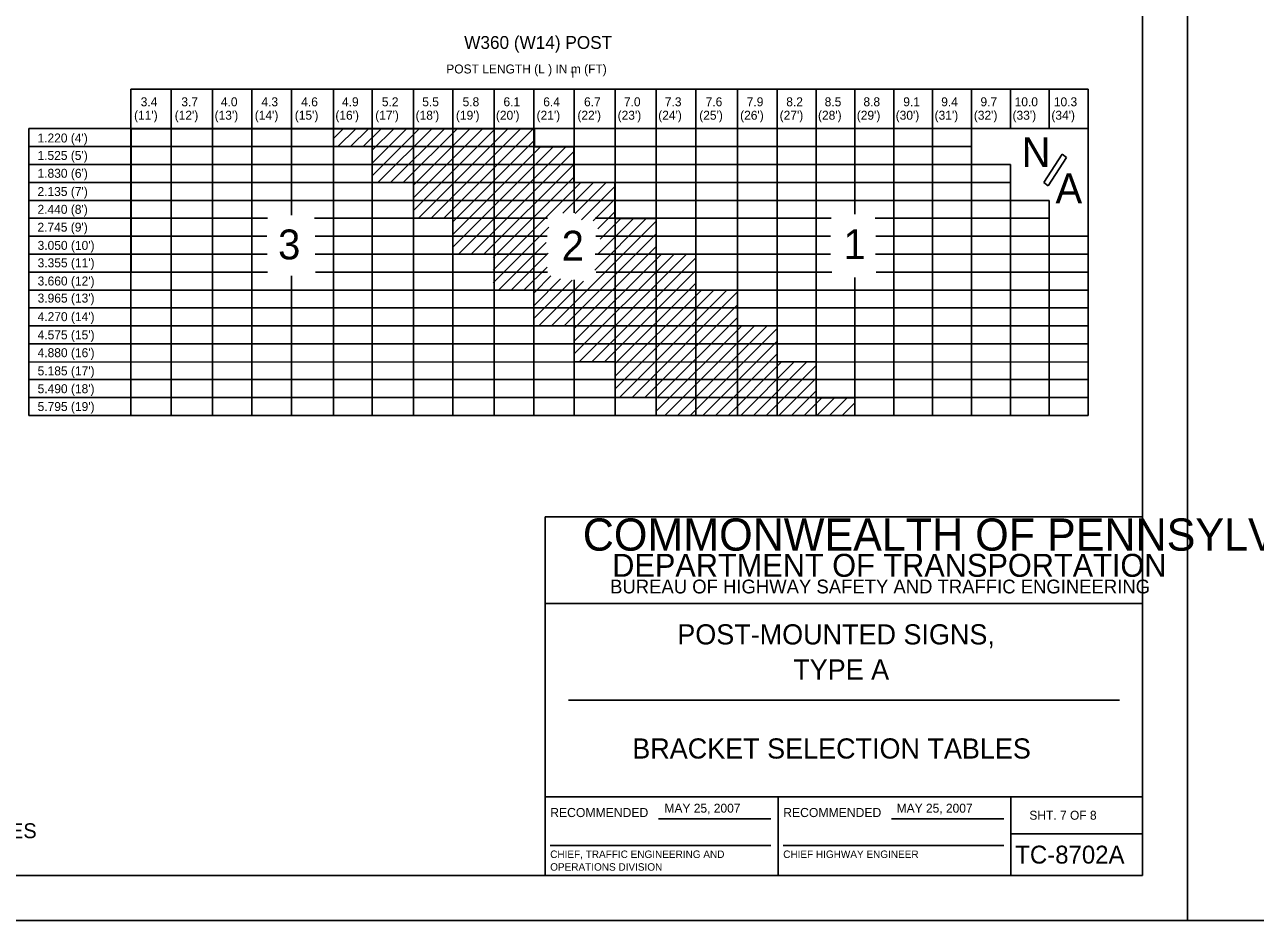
# Model space of a CAD drawing. Extents: x 637580 to 641008, y 294594 to 295782.
# Drawn here: x 639714 to 640126.1, y 294593.6 to 294893.4 of the extents above; entities that cross this region are included whole.
import ezdxf

# ---------------------------------------------------------------- set-up
doc = ezdxf.new("R2010")
doc.units = 0
for name, color, linetype in [('1', 7, 'Continuous'), ('2', 7, 'Continuous'), ('PLT-BNDY', 7, 'Continuous')]:
    doc.layers.add(name, color=color, linetype=linetype)

msp = doc.modelspace()

# ---------------------------------------------------------------- linework, layer by layer
at = {"layer": '1'}
for p, q in [((640088.31, 294608.63), (640088.31, 295172.63)), ((639888.31, 294608.63), (639888.31, 294728.63)), ((639888.31, 294728.63), (640088.31, 294728.63)), ((640088.31, 294699.63), (639888.31, 294699.63)), ((639896.06, 294667.31), (640080.56, 294667.31)), ((639888.31, 294635), (640088.31, 294635)), ((639966.31, 294635), (639966.31, 294608.63)), ((640044.19, 294608.63), (640044.19, 294635)), ((639926.24, 294627.57), (639963.87, 294627.57)), ((640004.24, 294627.57), (640041.87, 294627.57)), ((640044.19, 294622.63), (640088.31, 294622.63)), ((639889.99, 294618.68), (639963.87, 294618.68)), ((639967.99, 294618.68), (640041.87, 294618.68)), ((640088.31, 294608.63), (639302.31, 294608.63)), ((639302.31, 294608.63), (639888.31, 294608.63))]:
    msp.add_line(p, q, dxfattribs=at)
at = {"layer": '2'}
for p, q in [((640070.04, 294871.85), (639749.64, 294871.85)), ((639749.64, 294871.85), (639749.64, 294762.59)), ((639763.15, 294871.85), (639763.15, 294762.59)), ((639776.9, 294871.85), (639776.9, 294762.59)), ((639790.16, 294871.85), (639790.16, 294762.59)), ((639803.42, 294871.85), (639803.42, 294829.67)), ((639817.42, 294871.85), (639817.42, 294762.59)), ((639830.43, 294871.85), (639830.43, 294762.59)), ((639844.19, 294871.85), (639844.19, 294762.59)), ((639857.44, 294871.85), (639857.44, 294762.59)), ((639871.2, 294871.85), (639871.2, 294762.59)), ((639884.46, 294871.85), (639884.46, 294762.59)), ((639897.97, 294871.85), (639897.97, 294830.38)), ((639911.72, 294871.85), (639911.72, 294762.59)), ((639925.48, 294871.85), (639925.48, 294762.59)), ((639938.74, 294871.85), (639938.74, 294762.59)), ((639952.74, 294871.85), (639952.74, 294762.59)), ((639966, 294871.85), (639966, 294762.59)), ((639979.01, 294871.85), (639979.01, 294762.59)), ((639992.01, 294871.85), (639992.01, 294829.95)), ((640005.02, 294871.85), (640005.02, 294762.59)), ((640018.02, 294871.85), (640018.02, 294762.59)), ((640031.03, 294871.85), (640031.03, 294762.59)), ((640044.03, 294871.85), (640044.03, 294858.59)), ((640057.04, 294871.85), (640057.04, 294858.59)), ((640070.04, 294871.85), (640070.04, 294762.59)), ((640070.04, 294858.59), (639715.41, 294858.59)), ((639715.41, 294858.59), (639715.41, 294762.59)), ((639749.75, 294858.57), (639749.64, 294762.59)), ((639817.45, 294858.57), (639749.75, 294858.57)), ((639817.45, 294858.57), (639817.45, 294852.59)), ((639822.94, 294858.57), (639817.45, 294858.57)), ((639817.45, 294855.34), (639820.68, 294858.57)), ((639818.92, 294852.57), (639824.92, 294858.57)), ((639884.7, 294858.57), (639822.94, 294858.57)), ((639823.16, 294852.57), (639829.16, 294858.57)), ((639827.41, 294852.57), (639833.41, 294858.57)), ((639830.64, 294851.56), (639837.65, 294858.57)), ((639830.64, 294847.32), (639841.89, 294858.57)), ((639830.64, 294843.07), (639846.13, 294858.57)), ((639832.34, 294840.53), (639850.38, 294858.57)), ((639836.58, 294840.53), (639854.62, 294858.57)), ((639840.82, 294840.53), (639858.86, 294858.57)), ((639844.19, 294839.65), (639863.1, 294858.57)), ((639844.19, 294835.41), (639867.35, 294858.57)), ((639844.19, 294831.17), (639871.59, 294858.57)), ((639845.85, 294828.59), (639875.83, 294858.57)), ((639850.1, 294828.59), (639880.07, 294858.57)), ((639854.34, 294828.59), (639884.32, 294858.57)), ((640031.03, 294858.59), (639884.46, 294858.59)), ((639884.7, 294852.53), (639884.7, 294858.57)), ((640031.03, 294858.59), (640070.04, 294858.59)), ((640031.03, 294846.59), (640031.03, 294858.59)), ((640070.04, 294858.59), (640070.04, 294822.59)), ((640031.03, 294852.59), (639715.41, 294852.59)), ((639817.45, 294852.59), (639830.43, 294852.59)), ((639830.43, 294852.59), (639830.43, 294840.59)), ((639857.44, 294827.46), (639884.7, 294854.72)), ((639857.44, 294823.21), (639886.76, 294852.53)), ((639857.44, 294818.97), (639891, 294852.53)), ((639859.27, 294816.56), (639895.25, 294852.53)), ((639897.85, 294852.53), (639884.7, 294852.53)), ((639897.85, 294840.58), (639897.85, 294852.53)), ((639863.52, 294816.56), (639897.85, 294850.89)), ((640044.03, 294846.59), (639715.41, 294846.59)), ((639867.76, 294816.56), (639897.85, 294846.65)), ((640044.03, 294846.59), (640031.03, 294846.59)), ((640044.03, 294834.59), (640044.03, 294846.59)), ((640044.03, 294846.59), (640044.03, 294762.59)), ((640044.03, 294840.59), (639715.41, 294840.59)), ((639830.43, 294840.59), (639844.19, 294840.59)), ((639844.19, 294840.59), (639844.19, 294828.59)), ((639870.92, 294815.47), (639897.85, 294842.41)), ((639870.92, 294811.23), (639900.26, 294840.58)), ((639894.21, 294830.28), (639904.51, 294840.58)), ((639911.66, 294840.58), (639897.85, 294840.58)), ((639898.32, 294830.15), (639908.75, 294840.58)), ((639911.66, 294828.55), (639911.66, 294840.58)), ((639900.44, 294828.03), (639911.66, 294839.24)), ((640057.04, 294834.59), (639715.41, 294834.59)), ((639904.35, 294827.69), (639911.66, 294835)), ((640057.04, 294834.59), (640044.03, 294834.59)), ((640057.04, 294822.59), (640057.04, 294834.59)), ((640057.04, 294834.59), (640057.04, 294762.59)), ((639795.35, 294828.59), (639715.41, 294828.59)), ((639889.05, 294828.59), (639811.04, 294828.59)), ((639844.19, 294828.59), (639857.44, 294828.59)), ((639857.44, 294828.59), (639857.44, 294816.59)), ((639890.42, 294792.55), (639925.48, 294827.61)), ((639904.89, 294811.26), (639922.14, 294828.52)), ((639983.99, 294828.59), (639905.03, 294828.59)), ((639905.94, 294825.04), (639911.66, 294830.76)), ((639905.98, 294816.59), (639917.9, 294828.52)), ((639906.74, 294821.59), (639913.66, 294828.52)), ((639925.47, 294828.55), (639911.66, 294828.55)), ((639925.47, 294816.58), (639925.47, 294828.55)), ((640057.04, 294828.59), (639998.77, 294828.59)), ((639870.92, 294806.99), (639889.54, 294825.62)), ((639894.66, 294792.55), (639925.48, 294823.37)), ((639795.16, 294822.59), (639715.41, 294822.59)), ((639817.42, 294822.59), (639811.33, 294822.59)), ((639888.94, 294822.59), (639817.42, 294822.59)), ((639872.73, 294804.55), (639888.69, 294820.51)), ((639897.94, 294791.58), (639925.48, 294819.12)), ((639925.48, 294822.59), (639905.26, 294822.59)), ((639983.86, 294822.59), (639925.48, 294822.59)), ((640070.04, 294822.59), (639999.03, 294822.59)), ((640070.04, 294822.59), (640057.04, 294822.59)), ((640070.04, 294762.59), (640070.04, 294822.59)), ((639795.2, 294816.59), (639715.41, 294816.59)), ((639817.42, 294816.59), (639811.29, 294816.59)), ((639888.82, 294816.59), (639817.42, 294816.59)), ((639857.44, 294816.59), (639871.2, 294816.59)), ((639871.2, 294816.59), (639871.2, 294804.59)), ((639876.97, 294804.55), (639889.32, 294816.9)), ((639897.94, 294787.34), (639927.11, 294816.52)), ((639897.94, 294783.1), (639931.36, 294816.52)), ((639899.56, 294780.48), (639935.66, 294816.58)), ((639903.81, 294780.48), (639938.74, 294815.41)), ((639925.48, 294816.59), (639905.03, 294816.59)), ((639938.74, 294816.58), (639925.47, 294816.58)), ((639983.86, 294816.59), (639932.66, 294816.59)), ((639938.74, 294804.59), (639938.74, 294816.58)), ((640070.04, 294816.59), (639998.9, 294816.59)), ((639881.21, 294804.55), (639888.92, 294812.26)), ((639908.05, 294780.48), (639938.74, 294811.17)), ((639795.35, 294810.59), (639715.41, 294810.59)), ((639803.42, 294809.34), (639803.42, 294762.59)), ((639817.42, 294810.59), (639811.38, 294810.59)), ((639889.05, 294810.59), (639817.42, 294810.59)), ((639884.69, 294803.79), (639890.25, 294809.35)), ((639884.69, 294799.54), (639893.46, 294808.32)), ((639884.69, 294795.3), (639897.3, 294807.92)), ((639886.18, 294792.55), (639901.18, 294807.55)), ((639897.97, 294808.01), (639897.97, 294762.59)), ((639984.25, 294810.59), (639905.37, 294810.59)), ((639911.67, 294779.86), (639938.74, 294806.92)), ((639992.01, 294808.81), (639992.01, 294762.59)), ((640070.04, 294810.59), (639999.16, 294810.59)), ((639776.9, 294804.59), (639715.41, 294804.59)), ((640070.04, 294804.59), (639776.9, 294804.59)), ((639871.2, 294804.59), (639884.46, 294804.59)), ((639884.46, 294804.59), (639884.46, 294792.59)), ((639911.67, 294775.62), (639940.65, 294804.59)), ((639911.67, 294771.38), (639944.82, 294804.52)), ((639913.14, 294768.6), (639949.13, 294804.59)), ((639917.38, 294768.6), (639952.74, 294803.96)), ((639952.74, 294804.59), (639938.74, 294804.59)), ((639952.74, 294792.59), (639952.74, 294804.59)), ((639776.9, 294798.59), (639715.41, 294798.59)), ((640070.04, 294798.59), (639776.9, 294798.59)), ((639921.62, 294768.6), (639952.76, 294799.73)), ((639925.51, 294768.24), (639952.76, 294795.49)), ((639776.9, 294792.59), (639715.41, 294792.59)), ((640070.04, 294792.59), (639776.9, 294792.59)), ((639884.46, 294792.59), (639897.96, 294792.59)), ((639897.96, 294792.59), (639897.96, 294780.52)), ((639925.51, 294764), (639954.02, 294792.51)), ((639928.32, 294762.57), (639958.27, 294792.51)), ((639932.57, 294762.57), (639962.51, 294792.51)), ((639936.81, 294762.57), (639965.98, 294791.74)), ((639966.01, 294792.59), (639952.74, 294792.59)), ((639966.01, 294780.5), (639966.01, 294792.59)), ((639776.9, 294786.59), (639715.41, 294786.59)), ((640070.04, 294786.59), (639776.9, 294786.59)), ((639941.05, 294762.57), (639965.98, 294787.5)), ((639945.29, 294762.57), (639965.98, 294783.26)), ((640070.04, 294780.47), (639715.41, 294780.59)), ((639897.96, 294780.52), (639911.73, 294780.52)), ((639911.73, 294780.52), (639911.73, 294768.6)), ((639949.54, 294762.57), (639967.47, 294780.5)), ((639953.78, 294762.57), (639971.71, 294780.5)), ((639958.02, 294762.57), (639975.95, 294780.5)), ((639962.27, 294762.57), (639979.01, 294779.32)), ((639979.01, 294780.5), (639966.01, 294780.5)), ((639979.01, 294768.53), (639979.01, 294780.5)), ((640070.04, 294774.59), (639715.41, 294774.59)), ((639966.51, 294762.57), (639979.01, 294775.08)), ((639970.75, 294762.57), (639979.01, 294770.83)), ((640070.04, 294768.59), (639715.41, 294768.59)), ((639911.73, 294768.6), (639925.51, 294768.6)), ((639925.51, 294768.6), (639925.51, 294762.57)), ((639974.99, 294762.57), (639980.95, 294768.53)), ((639992.02, 294768.53), (639979.01, 294768.53)), ((639979.24, 294762.57), (639985.19, 294768.53)), ((639983.48, 294762.57), (639989.44, 294768.53)), ((639987.72, 294762.57), (639992.02, 294766.87)), ((639992.02, 294762.57), (639992.02, 294768.53)), ((640070.04, 294762.59), (639715.41, 294762.59)), ((639749.64, 294762.59), (639925.48, 294762.59)), ((639925.51, 294762.57), (639992.02, 294762.57)), ((639991.96, 294762.57), (639992.02, 294762.62)), ((640070.04, 294762.59), (639992.01, 294762.59))]:
    msp.add_line(p, q, dxfattribs=at)
for points in [[(640055.28, 294840.56), (640061.43, 294850)], [(640056.7, 294839.45), (640062.85, 294848.9)], [(640062.85, 294848.9), (640061.43, 294850)], [(640056.7, 294839.45), (640055.28, 294840.56)]]:
    msp.add_lwpolyline(points, dxfattribs=at)
at = {"layer": 'PLT-BNDY'}
for points in [[(639262.31, 295187.63), (640103.31, 295187.63), (640103.31, 294593.63), (639262.31, 294593.63)], [(640103.31, 295187.63), (640944.31, 295187.63), (640944.31, 294593.63), (640103.31, 294593.63)]]:
    msp.add_lwpolyline(points, close=True, dxfattribs=at)

# ---------------------------------------------------------------- texts
at = {"layer": '1'}
for s, height, p in [('COMMONWEALTH OF PENNSYLVANIA', 10.7828, (639900.9, 294717.36)), ('DEPARTMENT OF TRANSPORTATION', 7.6837, (639910.76, 294708.61)), ('BUREAU OF HIGHWAY SAFETY AND TRAFFIC ENGINEERING', 4.6253, (639910.04, 294703.04)), ('POST-MOUNTED SIGNS,', 6.75, (639932.54, 294685.97)), ('TYPE A', 6.75, (639971.35, 294674.22)), ('BRACKET SELECTION TABLES', 6.75, (639917.47, 294647.78)), ('RECOMMENDED', 3.048, (639889.99, 294628.2)), ('RECOMMENDED', 3.048, (639967.99, 294628.2)), ('SHT. 7 OF 8', 3, (640050.4, 294627.31)), ('TC-8702A', 6, (640045.68, 294612.63)), ('CHIEF, TRAFFIC ENGINEERING AND', 2.5, (639889.99, 294614.51)), ('CHIEF HIGHWAY ENGINEER', 2.5, (639967.99, 294614.51)), ('OPERATIONS DIVISION', 2.5, (639889.99, 294610.26))]:
    msp.add_text(s, height=height, dxfattribs=at).set_placement(p)
at = {"layer": '2'}
for s, height, p in [('W360 (W14) POST', 4.3, (639861.2, 294885.29)), ('POST LENGTH (L ) IN m (FT)', 3, (639855.2, 294877.06)), ('T', 2, (639896.74, 294875.68)), ('3.4', 3, (639752.91, 294866.08)), ('3.7', 3, (639766.52, 294866.08)), ('4.0', 3, (639779.75, 294866.08)), ('4.3', 3, (639793.32, 294866.08)), ('4.6', 3, (639806.64, 294866.08)), ('4.9', 3, (639820.29, 294866.08)), ('5.2', 3, (639833.63, 294866.08)), ('5.5', 3, (639847.15, 294866.08)), ('5.8', 3, (639860.66, 294866.08)), ('6.1', 3, (639874.35, 294866.08)), ('6.4', 3, (639887.66, 294866.08)), ('6.7', 3, (639901.32, 294866.08)), ('7.0', 3, (639914.67, 294866.08)), ('7.3', 3, (639928.37, 294866.08)), ('7.6', 3, (639942.03, 294866.08)), ('7.9', 3, (639955.78, 294866.08)), ('8.2', 3, (639969.02, 294866.08)), ('8.5', 3, (639981.87, 294866.08)), ('8.8', 3, (639994.85, 294866.08)), ('9.1', 3, (640008.19, 294866.08)), ('9.4', 3, (640020.89, 294866.08)), ('9.7', 3, (640034.03, 294866.08)), ('10.0', 3, (640045.47, 294866.08)), ('10.3', 3, (640058.59, 294866.08)), ("(11')", 3, (639750.69, 294861.58)), ("(12')", 3, (639764.29, 294861.58)), ("(13')", 3, (639777.65, 294861.58)), ("(14')", 3, (639791.09, 294861.58)), ("(15')", 3, (639804.49, 294861.58)), ("(16')", 3, (639818.07, 294861.58)), ("(17')", 3, (639831.41, 294861.58)), ("(18')", 3, (639844.93, 294861.58)), ("(19')", 3, (639858.43, 294861.58)), ("(20')", 3, (639871.81, 294861.58)), ("(21')", 3, (639885.43, 294861.58)), ("(22')", 3, (639899.1, 294861.58)), ("(23')", 3, (639912.56, 294861.58)), ("(24')", 3, (639926.15, 294861.58)), ("(25')", 3, (639939.88, 294861.58)), ("(26')", 3, (639953.57, 294861.58)), ("(27')", 3, (639966.8, 294861.58)), ("(28')", 3, (639979.64, 294861.58)), ("(29')", 3, (639992.62, 294861.58)), ("(30')", 3, (640005.64, 294861.58)), ("(31')", 3, (640018.67, 294861.58)), ("(32')", 3, (640031.8, 294861.58)), ("(33')", 3, (640044.76, 294861.58)), ("(34')", 3, (640057.76, 294861.58)), ("1.220 (4')", 3, (639718.36, 294853.96)), ('N', 10, (640047.79, 294845.72)), ("1.525 (5')", 3, (639718.36, 294848.11)), ("1.830 (6')", 3, (639718.37, 294842.15)), ('A', 10, (640059.15, 294833.61)), ("2.135 (7')", 3, (639718.36, 294836.05)), ("2.440 (8')", 3, (639718.36, 294830.09)), ("2.745 (9')", 3, (639718.35, 294824.12)), ('3', 10, (639798.91, 294814.84)), ('2', 10, (639893.84, 294814.42)), ('1', 10, (639988.19, 294814.92)), ("3.050 (10')", 3, (639718.4, 294818.03)), ("3.355 (11')", 3, (639718.4, 294812.19)), ("3.660 (12')", 3, (639718.4, 294806.1)), ("3.965 (13')", 3, (639718.4, 294800.39)), ("4.270 (14')", 3, (639718.4, 294794.17)), ("4.575 (15')", 3, (639718.4, 294788.08)), ("4.880 (16')", 3, (639718.4, 294782.11)), ("5.185 (17')", 3, (639718.4, 294776.02)), ("5.490 (18')", 3, (639718.4, 294770.06)), ("5.795 (19')", 3, (639718.4, 294764.09)), ('MAY 25, 2007', 3, (639928.25, 294629.67)), ('MAY 25, 2007', 3, (640005.97, 294629.67)), ('B-650 BRACKET TABLES', 5, (639639.3, 294621.13))]:
    msp.add_text(s, height=height, dxfattribs=at).set_placement(p)

doc.saveas('drawing.dxf')
